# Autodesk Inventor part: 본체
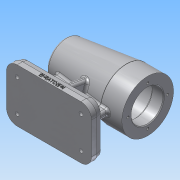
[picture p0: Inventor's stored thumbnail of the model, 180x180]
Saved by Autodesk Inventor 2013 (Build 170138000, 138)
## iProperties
Created: 2017-01
Part Number: 본체
Material: 알루미늄 6061
Document SubType Name: Modeling
Designer: Administrator
Density: 2.71 g/cm^3
Mass: 795.027 g
Surface Area: 662.225 cm^2
Volume: 293.368 cm^3
Author: Administrator
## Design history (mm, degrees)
sketch "스케치1"
  geometry: L1 (-56, 0)-(56, 0); L2 (-52.27, 24.144)-(28, 34); L3 (28, 34)-(56, 34); L4 (56, 34)-(56, 0); A1 r 80 centre (24, 0) between (-52.27, 24.144) and (-56, 0); 1 further point
  constraints: 8 end point, 2 point on circle, 1 centre point, 1 horizontal, 1 midpoint, 1 parallel, 1 perpendicular, 1 point on line
  dimensions: "d0" = 112 distance of L1.start L1.end; "d2" = 56 distance of point (0, 0) L1.start; "d3" = 28 distance of L2.end L3.end; "d4" = 7 deg angle of L3 L2; "d5" = 80 radius of A1; "d6" = 68 diameter of L3 L1
revolve "회전1" sketch "스케치1" stored, may be unused: angle "d7" = 90 deg
sketch "스케치2"
  geometry: C1 r 34 at (0, 0) reference
hole "구멍1" sketch "스케치2" at (0, 0) diameter "d8" = 42; stored, may be unused: countersink angle "d12" = 90 deg, drill point angle "d14" = 0 deg; dims "d9" = 6, "d10" = 42, "d11" = 15, "d13" = 15
sketch "스케치3"
  geometry: C1 r 21 at (0, 0) reference
hole "구멍2" sketch "스케치3" at (0, 0) diameter "d15" = 42; stored, may be unused: countersink angle "d19" = 90 deg, drill point angle "d21" = 0 deg; dims "d16" = 6, "d17" = 48, "d18" = 54, "d20" = 66
sketch "스케치4"
  geometry: C1 r 21 at (0, 0) reference
hole "구멍3" sketch "스케치4" at (0, 0) diameter "d22" = 32; stored, may be unused: countersink angle "d26" = 90 deg, drill point angle "d28" = 0 deg; dims "d23" = 6, "d24" = 35, "d25" = 18, "d27" = 22
sketch "스케치5"
  geometry: C1 r 16 at (0, 0) reference
hole "구멍4" sketch "스케치5" at (0, 0) diameter "d29" = 21; stored, may be unused: countersink angle "d33" = 90 deg, drill point angle "d35" = 0 deg; dims "d30" = 6, "d31" = 35, "d32" = 18, "d34" = 3
fillet "모깎기1" dims "d36" = 3
fillet "모깎기2" dims "d37" = 3
sketch "스케치9"
  geometry: C1 r 21 at (0, 0) reference; C2 r 24 at (0, 0) reference; 1 further point
  constraints: 1 vertical alignment
  dimensions: "d38" = 26 distance of C2.centre point (0, 26)
hole "구멍5" sketch "스케치9" at (0, 26) diameter "d39" = 3.242; stored, may be unused: countersink angle "d43" = 90 deg, drill point angle "d45" = 118 deg; dims "d40" = 8, "d41" = 35, "d42" = 18, "d44" = 11
node "작업 평면1"
sketch "스케치10"
  geometry: L1 (56, 35)-(-56, 35); L2 (-56, 35)-(-56, -35); L3 (-56, -35)-(56, -35); L4 (56, -35)-(56, 35); L5 (56, 35)-(-56, -35); L6 (-56, 35)-(56, -35); 4 further points
  constraints: 12 end point, 4 midpoint, 2 parallel, 1 horizontal, 1 horizontal alignment, 1 perpendicular, 1 vertical alignment
  dimensions: "d50" = 112 distance of L1.start L1.end; "d52" = 70 distance of L1.end L2.end
extrude "돌출1" join sketch "스케치10" distance "d53" = 7; taper "d54" = 0 deg
fillet "모깎기12" dims "d119" = 14
sketch "스케치23"
  geometry: L1 (42, 35)-(-42, 35) reference; L2 (-56, 21)-(-56, -21) reference; L3 (-42, -35)-(42, -35) reference; L4 (56, -21)-(56, 21) reference; A1 r 14 centre (42, 21) between (56, 21) and (42, 35) reference; A2 r 14 centre (-42, 21) between (-42, 35) and (-56, 21) reference; A3 r 14 centre (-42, -21) between (-56, -21) and (-42, -35) reference; A4 r 14 centre (42, -21) between (42, -35) and (56, -21) reference; 1 further point
extrude "돌출5" join sketch "스케치23" distance "d120" = 7; taper "d121" = -15 deg
sketch "스케치24"
  geometry: L1 (42, -33.124)-(-42, -33.124) reference; L2 (-38, 4)-(38, 4); L3 (38, 4)-(38, -4); L4 (38, -4)-(-38, -4); L5 (-38, -4)-(-38, 4); L6 (-56, 21)-(-56, -21) reference; L7 (56, -21)-(56, 21) reference; L8 (42, 35)-(-42, 35) reference; 2 further points
  constraints: 8 end point, 3 parallel, 1 horizontal alignment, 1 midpoint, 1 perpendicular
  dimensions: "d122" = 18 distance between parallel lines of L5 L6; "d123" = 18 distance between parallel lines of L7 L3; "d124" = 31 distance between parallel lines of L8 L2
extrude "돌출6" join sketch "스케치24" stored distance "d125" = 7; taper "d126" = 0 deg
node "작업 평면2"
sketch "스케치27" dims "d130" = 10
  geometry: L1 (-39.113, 26)-(-36.226, 21); L2 (-36.226, 21)-(-39.113, 16); L3 (-39.113, 16)-(-44.887, 16); L4 (-44.887, 16)-(-47.774, 21); L5 (-47.774, 21)-(-44.887, 26); L6 (-44.887, 26)-(-39.113, 26); L7 (-39.113, -16)-(-36.226, -21); L8 (-36.226, -21)-(-39.113, -26); L9 (-39.113, -26)-(-44.887, -26); L10 (-44.887, -26)-(-47.774, -21); L11 (-47.774, -21)-(-44.887, -16); L12 (-44.887, -16)-(-39.113, -16); L13 (44.887, 26)-(47.774, 21); L14 (47.774, 21)-(44.887, 16); L15 (44.887, 16)-(39.113, 16); L16 (39.113, 16)-(36.226, 21); L17 (36.226, 21)-(39.113, 26); L18 (39.113, 26)-(44.887, 26); L19 (44.887, -16)-(47.774, -21); L20 (47.774, -21)-(44.887, -26); L21 (44.887, -26)-(39.113, -26); L22 (39.113, -26)-(36.226, -21); L23 (36.226, -21)-(39.113, -16); L24 (39.113, -16)-(44.887, -16); A1 r 12.124 centre (42, 21) between (54.124, 21) and (42, 33.124) reference; A2 r 12.124 centre (-42, 21) between (-42, 33.124) and (-54.124, 21) reference; A3 r 12.124 centre (-42, -21) between (-54.124, -21) and (-42, -33.124) reference; A4 r 12.124 centre (42, -21) between (42, -33.124) and (54.124, -21) reference; 17 further points
  constraints: 48 end point, 11 coincident, 8 vertical alignment, 4 midpoint, 60 other
  dimensions: "d127" = 42 distance of point (-42, -21) point (-42, 21); "d129" = 84 distance of point (42, -21) point (-42, -21)
extrude "돌출7" cut sketch "스케치27" distance "d131" = 4; taper "d132" = 0 deg
sketch "스케치28"
  geometry: L1 (-44.887, 26)-(-39.113, 26) reference; 4 further points
  constraints: 1 horizontal alignment, 1 midpoint, 1 vertical alignment
hole "구멍7" sketch "스케치28" at (-42, 21) diameter "d133" = 5; stored, may be unused: countersink angle "d137" = 90 deg, drill point angle "d139" = 118 deg; dims "d134" = 8, "d135" = 35, "d136" = 18, "d138" = 11
fillet "모깎기5" dims "d106" = 3
fillet "모깎기6" dims "d107" = 0.3
fillet "모깎기10" dims "d113" = 3
sketch "스케치22"
  geometry: L1 (0, 0)-(84, 0); L2 (98, 0)-(98, 7); L3 (84, 7)-(84, 0) reference; L4 (0, 7)-(84, 7) reference; L5 (0, 0)-(0, 7) reference; L6 (0, 0)-(84, 0) reference; 2 further points
  constraints: 4 end point, 1 other
  dimensions: "d115" = 4 distance from line of L1 point (42, 4); "d116" = 56 distance from line of L2 point (42, 4)
feature "엠보싱1" sketch "스케치22" dims "d0" = 112, "d2" = 56, "d3" = 28, "d4" = 7 deg, "d5" = 80, "d6" = 68, "d117" = 0.5, "d118" = 0
sketch "스케치29"
  geometry: L1 (-60, 23)-(-37.773, 19.081); L2 (-60, -23)-(-38.09, -19.137); L3 (-60, -33.124)-(-67, -35) reference; L4 (-67, -35)-(-74, -35) reference; L5 (-74, -35)-(-74, 35) reference; L6 (-74, 35)-(-68.423, 35) reference; L7 (-68.423, 35)-(-68.423, 35.5) reference; L8 (-68.423, 35.5)-(-68.092, 35.5) reference; L9 (-68.092, 35.5)-(-68.092, 35) reference; L10 (-68.092, 35)-(-67, 35) reference; L11 (-67, 35)-(-60, 33.124) reference; L12 (-60, 33.124)-(-60, 4) reference; L13 (-60, 4)-(-30.299, 4) reference; L14 (-30.299, -4)-(-60, -4) reference; L15 (-60, -4)-(-60, -33.124) reference; C1 r 24 at (0, 0) reference; A1 r 30.562 centre (0, 0) between (-30.299, -4) and (-30.299, 4) reference; 1 further point
  constraints: 4 end point, 2 point on line
  dimensions: "d146" = 100 deg angle of L12 L1; "d147" = 100 deg angle of L15 L2; "d148" = 12 distance from line of L1.start L6; "d149" = 12 distance from line of L2.start L4
  node "절단 모서리 투영6"
feature "리브3" dims "d150" = 1, "d151" = 8, "d152" = 0, "d153" = 0, "d154" = 1, "d155" = 1
feature "리브4" dims "d156" = 1, "d157" = 8, "d158" = 0, "d159" = 0, "d160" = 1, "d161" = 1
fillet "모깎기13" dims "d162" = 3
fillet "모깎기14" dims "d163" = 3
fillet "모깎기15" dims "d164" = 3
chamfer "모따기1" distance "d165" = 1; stored, may be unused: second distance "d166" = 2, angle "d167" = 45 deg
fillet "모깎기16" dims "d168" = 1
node "솔리드1"
pattern_circular "원형 패턴1" dims angle "d47" = 360 deg
pattern_linear "직사각형 패턴2" dims "d142" = 42, "d145" = 84
other parameters: "d49" = -74
